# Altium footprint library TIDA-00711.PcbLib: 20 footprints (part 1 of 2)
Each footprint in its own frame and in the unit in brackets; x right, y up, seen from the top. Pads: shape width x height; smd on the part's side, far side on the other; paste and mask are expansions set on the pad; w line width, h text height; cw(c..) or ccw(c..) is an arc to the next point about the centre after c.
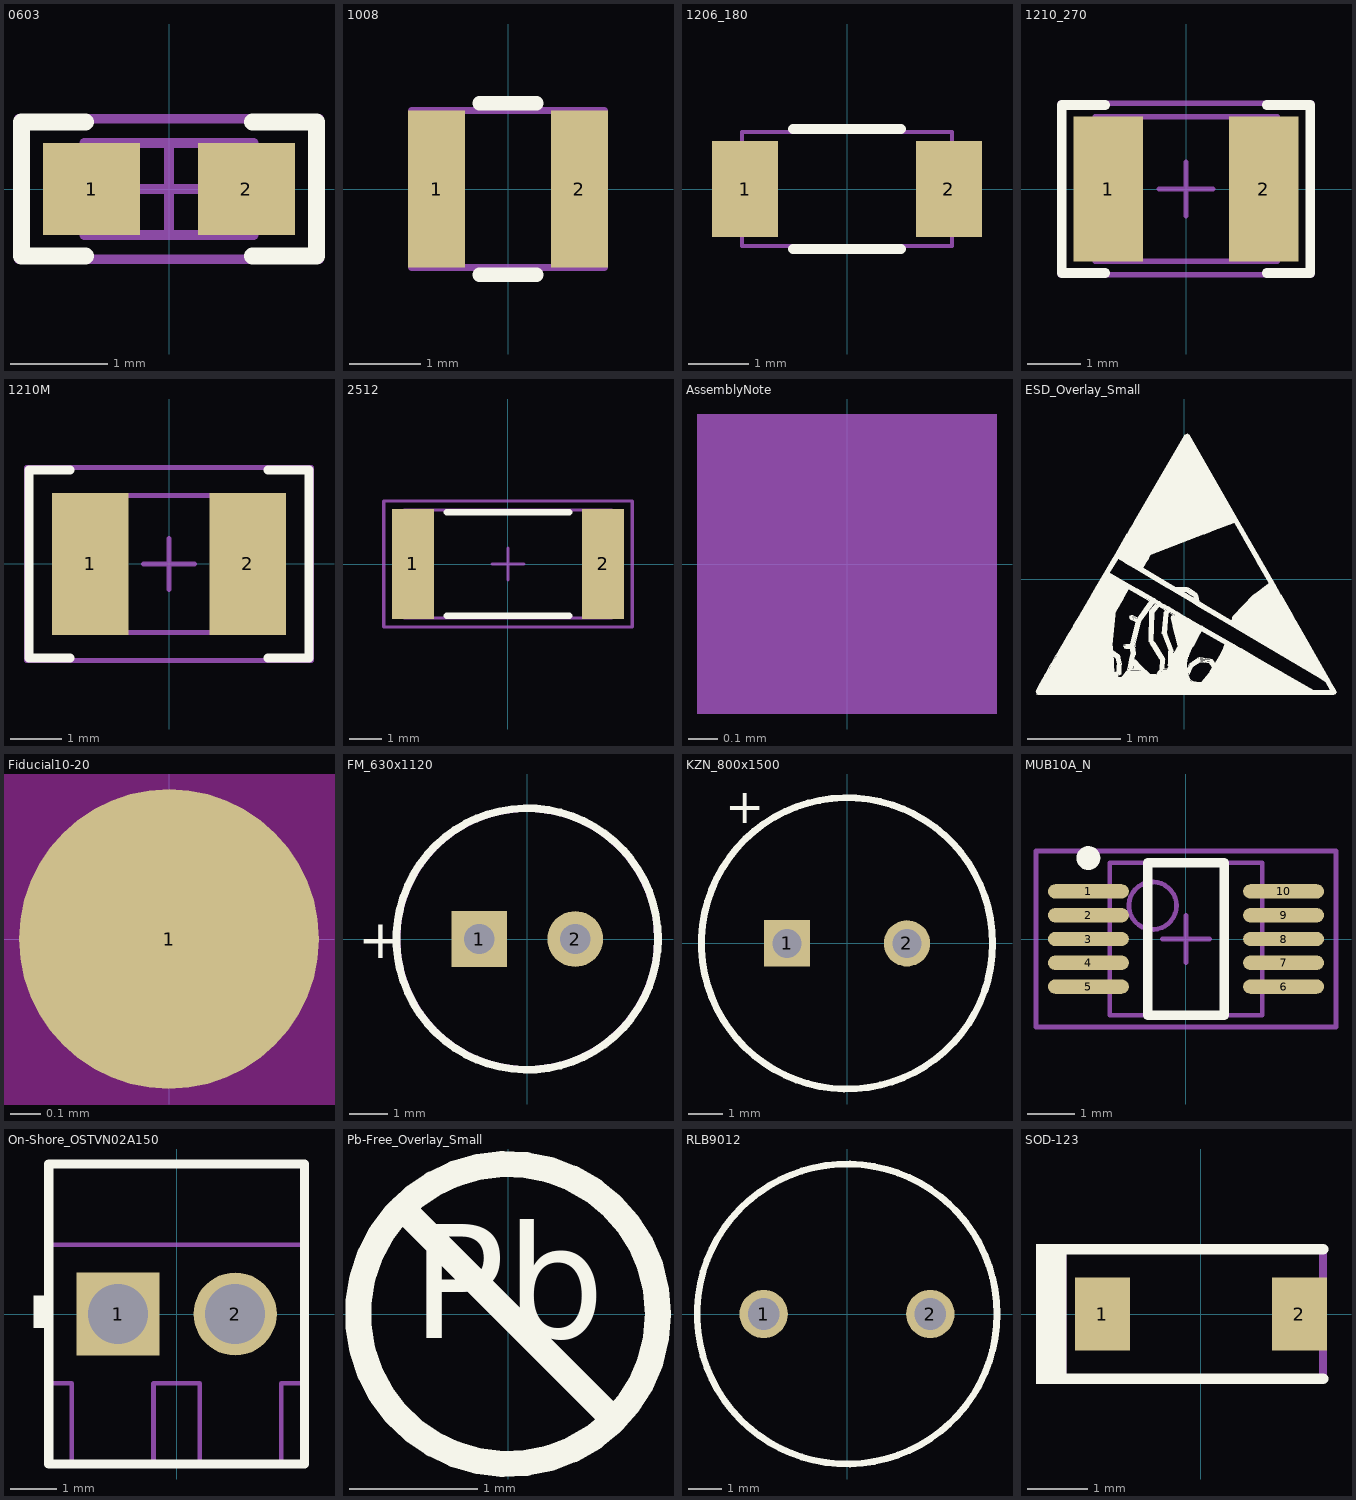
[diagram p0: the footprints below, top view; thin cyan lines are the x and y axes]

## 0603 [mm] "0603 from SM-752 data"
height 1
pads (2):
  rect 1x0.95 smd: 1(-0.8,0) 2(0.8,0)
Top Overlay:
  lines w0.178: -0.864,-0.691 -1.524,-0.691 -1.524,0.693 -0.864,0.693 ; 0.864,-0.691 1.524,-0.691 1.524,0.693 0.864,0.693
Mechanical 5:
  lines w0.1: -1.55,-0.725 -1.55,0.725 1.55,0.725 1.55,-0.725 -1.55,-0.725
  text ".Designator" at -1.143,-0.483 h1.02
Mechanical 13:
  lines w0.1: -0.55,-0.475 -0.55,0.475 ; 0.55,-0.475 0.55,0.475 ; -0.875,-0.475 0.875,-0.475 0.875,0.475 -0.875,0.475 -0.875,-0.475
Mechanical 15:
  lines w0.1: -0.475,0 0.475,0 ; 0,-0.475 0,0.475 ; -1.55,-0.725 1.55,-0.725 1.55,0.725 -1.55,0.725 -1.55,-0.725
3D body: height 1, standoff 0, extent -0.874,-0.474 -0.551,0.474
3D body: height 1, standoff 0, extent -0.549,-0.474 0.549,0.474
3D body: height 1, standoff 0, extent 0.551,-0.474 0.874,0.474

## 1008 [mm] "SMD, Body 2.5x2mm, Height 1.2mm"
height 1.2
pads (2):
  rect 0.8x2.2 smd: 1(-1,0) 2(1,0)
Top Overlay:
  lines w0.2: -0.4,-1.2 0.4,-1.2 ; -0.4,1.2 0.4,1.2
Mechanical 5:
  lines w0.1: -1.35,-1.1 -1.35,1.1 1.35,1.1 1.35,-1.1 -1.35,-1.1
  text ".Designator" at 0.559,-0.835 h1.02
3D body: height 1.2, standoff 0, extent -1.349,-1.099 -0.551,1.099
3D body: height 1.2, standoff 0, extent 0.551,-1.099 1.349,1.099
3D body: height 1.2, standoff 0, extent -0.549,-1.099 0.549,1.099

## 1206_180 [mm] "1206_180"
height 1.8
pads (2):
  rect 1.1x1.6 smd: 1(-1.7,0) 2(1.7,0)
Top Overlay:
  lines w0.17: -0.9,-1 0.9,-1 ; -0.9,1 0.9,1
Mechanical 5:
  lines w0.07: -1.75,-0.95 1.75,-0.95 1.75,0.95 -1.75,0.95 -1.75,-0.95
  text ".Designator" at -1.219,-0.457 h1.02
3D body: height 1.8, standoff 0, extent -1.749,-0.949 -1.301,0.949
3D body: height 1.8, standoff 0, extent -1.299,-0.949 1.299,0.949
3D body: height 1.8, standoff 0, extent 1.301,-0.949 1.749,0.949

## 1210_270 [mm] "1210"
height 2.7
pads (2):
  rect 1.3x2.7 smd: 1(-1.45,0) 2(1.45,0)
Top Overlay:
  lines w0.178: -1.511,-1.568 -2.316,-1.568 -2.316,1.568 -1.511,1.568 ; 1.511,-1.568 2.316,-1.568 2.316,1.568 1.511,1.568
Mechanical 5:
  lines w0.1: -1.7,-1.35 1.7,-1.35 1.7,1.35 -1.7,1.35 -1.7,-1.35
  text ".Designator" at 0.508,-0.66 h1.02
Mechanical 13:
  lines w0.1: -1.2,-1.35 -1.2,1.35 ; 1.2,-1.35 1.2,1.35 ; -1.7,-1.35 -1.7,1.35 1.7,1.35 1.7,-1.35 -1.7,-1.35
Mechanical 15:
  lines w0.1: -0.5,0 0.5,0 ; 0,-0.5 0,0.5 ; -2.35,-1.6 -2.35,1.6 2.35,1.6 2.35,-1.6 -2.35,-1.6
3D body: height 2.7, standoff 0, extent -1.699,-1.349 -1.201,1.349
3D body: height 2.7, standoff 0, extent -1.199,-1.349 1.199,1.349
3D body: height 2.7, standoff 0, extent 1.201,-1.349 1.699,1.349

## 1210M [mm] "1210 from SM-752 data"
height 1.35
pads (2):
  rect 1.5x2.8 smd: 1(-1.55,0) 2(1.55,0)
Top Overlay:
  lines w0.178: -1.95,-1.85 -2.75,-1.85 -2.75,1.85 -1.95,1.85 ; 1.95,-1.85 2.75,-1.85 2.75,1.85 1.95,1.85
Mechanical 5:
  lines w0.1: -1.7,-1.35 1.7,-1.35 1.7,1.35 -1.7,1.35 -1.7,-1.35
  text ".Designator" at 0.66,0.483 h1.02
Mechanical 13:
  lines w0.1: -1.2,-1.35 -1.2,1.35 ; 1.2,-1.35 1.2,1.35 ; -1.7,-1.35 -1.7,1.35 1.7,1.35 1.7,-1.35 -1.7,-1.35
Mechanical 15:
  lines w0.1: -0.5,0 0.5,0 ; 0,-0.5 0,0.5 ; -2.8,-1.9 2.8,-1.9 2.8,1.9 -2.8,1.9 -2.8,-1.9
3D body: height 1.35, standoff 0, extent -1.699,-1.349 -1.201,1.349
3D body: height 1.35, standoff 0, extent -1.199,-1.349 1.199,1.349
3D body: height 1.35, standoff 0, extent 1.201,-1.349 1.699,1.349

## 2512 [mm] "Chip Resistor, Body 6.3x3.2mm, IPC Medium Density"
height 0.71
pads (2):
  rect 1.3x3.4 smd: 1(-2.95,0) 2(2.95,0)
Top Overlay:
  lines w0.2: -1.9,-1.6 1.9,-1.6 ; -1.9,1.6 1.9,1.6
Mechanical 5:
  lines w0.1: -3.225,-1.675 3.225,-1.675 3.225,1.675 -3.225,1.675 -3.225,-1.675
  text ".Designator" at 0.996,-0.836 h1.02
Mechanical 13:
  lines w0.1: -2.463,-1.675 -2.463,1.675 ; 2.463,-1.675 2.463,1.675 ; -3.225,-1.675 3.225,-1.675 3.225,1.675 -3.225,1.675 -3.225,-1.675
Mechanical 15:
  lines w0.1: -0.5,0 0.5,0 ; 0,-0.5 0,0.5 ; -3.85,-1.95 3.85,-1.95 3.85,1.95 -3.85,1.95 -3.85,-1.95
3D body: height 0.71, standoff 0, extent -3.224,-1.674 -2.464,1.674
3D body: height 0.71, standoff 0, extent -2.462,-1.674 2.462,1.674
3D body: height 0.71, standoff 0, extent 2.464,-1.674 3.224,1.674

## AssemblyNote [mm] "Assembly Note"
Mechanical 5:
  rectangle: -0.508,-0.508 0.508,0.508
  text ".Designator" at -4.191,-0.508 h1.02
  text ".Comment" at 1.143,-0.508 h1.02

## ESD_Overlay_Small [mm]
height 28.5
Top Overlay:
  drawing of 901 lines, arcs and shapes, not listed

## Fiducial10-20 [mm]
height 28.5
pads (1):
  round 1 smd mask+0.5: 1(0,0)
Top Layer keep-out:
  circle w1.178: c0,0 r0.5

## FM_630x1120 [mm] "PANASONIC"
height 12.7
pads (2):
  rect 1.45x1.45 hole 0.787: 1(-1.25,0)
  round 1.45 hole 0.787: 2(1.25,0)
Top Overlay:
  circle w0.2: c0,0 r3.401
  text "+" at -4.4,-0.5 h1.02
Mechanical 5:
  circle w0.1: c0,0 r3.35
  text "+" at -4.4,-0.5 h1.02
  text ".Designator" at 0.965,0.33 h1.02
3D body: height 12.71, standoff -4, extent -3.373,-3.394 3.397,3.395

## KZN_800x1500 [mm] "TH, 2-Leads, Dia 8mm, Pin Spacing 3.5mm"
height 16.5
pads (2):
  rect 1.35x1.35 hole 0.85: 1(-1.75,0)
  round 1.35 hole 0.85: 2(1.75,0)
Top Overlay:
  circle w0.2: c0,0 r4.25
  text "+" at -3.556,3.505 h1
Mechanical 5:
  circle w0.1: c0,0 r4.25
  text "+" at -3.556,3.505 h1
  text ".Designator" at 0.508,-1.067 h1.02
3D body: height 16.51, standoff -3, extent -4.217,-4.243 4.244,4.243

## MUB10A_N [mm] "TSSOP, 10-Leads, Body 3x3mm, Pitch 0.5mm, IPC Medium Density"
height 1.09
pads (10):
  oval 1.7x0.3 smd: 1(-2.05,1) 2(-2.05,0.5) 3(-2.05,0) 4(-2.05,-0.5) 5(-2.05,-1) 6(2.05,-1) 7(2.05,-0.5) 8(2.05,0) 9(2.05,0.5) 10(2.05,1)
Top Overlay:
  circle w0.25: c-2.05,1.7 r0.125
  lines w0.2: -0.8,-1.6 0.8,-1.6 0.8,1.6 -0.8,1.6 -0.8,-1.6
Mechanical 5:
  text ".Designator" at -0.508,0.559 h1.02
Mechanical 13:
  circle w0.1: c-0.7,0.7 r0.5
  lines w0.1: -1.6,-1.6 1.6,-1.6 1.6,1.6 -1.6,1.6 -1.6,-1.6
Mechanical 15:
  lines w0.1: -0.5,0 0.5,0 ; 0,-0.5 0,0.5 ; -3.15,-1.85 3.15,-1.85 3.15,1.85 -3.15,1.85 -3.15,-1.85
3D body: height 1.09, standoff 0, extent -1.6,-1.6 1.6,1.6

## On-Shore_OSTVN02A150 [mm] "Terminal Block, 2.54mm, 2-pole, Brass, TH"
height 8.5
pads (2):
  rect 1.8x1.8 hole 1.3: 1(-1.27,0)
  round 1.8 hole 1.3: 2(1.27,0)
Top Overlay:
  rectangle: -3.1,-0.3 -2.8,0.4
  lines w0.2: -2.77,-3.25 -2.77,3.25 2.77,3.25 2.77,-3.25 -2.77,-3.25
Mechanical 5:
  lines w0.1: -2.77,-1.5 -2.27,-1.5 -2.27,-3.25 ; -2.77,1.5 2.77,1.5 ; -0.5,-3.25 -0.5,-1.5 0.5,-1.5 0.5,-3.25 ; 2.27,-3.25 2.27,-1.5 2.77,-1.5 ; -2.77,-3.25 2.77,-3.25 2.77,3.25 -2.77,3.25 -2.77,-3.25
  text ".Designator" at -0.612,-0.229 h1.02
3D body: height 0, standoff -2.5, extent -1.72,-0.2 -0.82,0.2
3D body: height 0, standoff -2.5, extent 0.82,-0.2 1.72,0.2
3D body: height 8.51, standoff 0, extent -2.014,-0.748 -0.52,0.749
3D body: height 8.51, standoff 0, extent 0.526,-0.748 2.02,0.749
3D body: height 1.6, standoff 0, extent -2.77,-3.25 2.77,3.25
3D body: height 4, standoff 0, extent 2.27,-3.25 2.77,-1.5
3D body: height 4, standoff 0, extent -0.5,-3.25 0.5,-1.5
3D body: height 4, standoff 0, extent -2.77,-3.25 -2.27,-1.5
3D body: height 4, standoff 0, extent -2.77,1.5 2.77,3.25
3D body: height 4, standoff 3, extent -2.27,-2 -0.5,-1.5
3D body: height 4, standoff 3, extent 0.5,-2 2.27,-1.5
3D body: height 3, standoff 0, extent -2.27,-2 -0.5,-1.5
3D body: height 3, standoff 0, extent 0.5,-2 2.27,-1.5
3D body: height 8.5, standoff 1.6, extent -2.77,-1.5 2.77,0
3D body: height 8.5, standoff 1.6, extent -2.77,0 2.77,1.5
3D body: height 8.5, standoff 4, extent -2.77,-2 2.77,-1.5
3D body: height 8.5, standoff 4, extent -2.77,1.5 2.77,2

## Pb-Free_Overlay_Small [mm]
height 28.5
Top Overlay:
  circle w0.203: c0,0 r1.168
  lines w0.203: -0.826,0.826 0.826,-0.826
  text "Pb" at -0.752,-0.48 h1.52

## RLB9012 [mm] "TH, 2-Leads, Dia 9mm, Pin Spacing 5mm"
height 12.2
pads (2):
  round 1.45 hole 0.95: 1(-2.5,0) 2(2.5,0)
Top Overlay:
  circle w0.2: c0,0 r4.5
Mechanical 5:
  circle w0.1: c0,0 r4.5
  text ".Designator" at 0.127,-0.61 h1.02
3D body: height 11, standoff -6, extent -4.6,-4.6 4.6,4.6

## SOD-123 [mm] "On Semi recommended land pattern"
height 1.35
pads (2):
  rect 0.915x1.22 smd: 1(-1.637,0) 2(1.637,0)
Top Overlay:
  rectangle: -2.743,-1.168 -2.235,1.168
  lines w0.178: -2.413,-1.079 2.032,-1.079 ; -2.413,1.079 2.032,1.079
Mechanical 5:
  rectangle: -2.743,-1.168 -2.235,1.168
  lines w0.127: -2.413,-1.079 2.032,-1.079 2.032,1.079 -2.413,1.079
  text ".Designator" at -1.118,-0.508 h1.02
3D body: height 1.35, standoff 0, extent -1.932,-0.9 1.932,0.9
